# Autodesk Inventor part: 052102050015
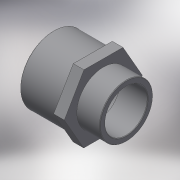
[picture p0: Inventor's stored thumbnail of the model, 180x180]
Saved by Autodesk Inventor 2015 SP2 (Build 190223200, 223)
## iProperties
Created: 2017-10
Part Number: 052102050015
Material: Generic
Description: PLASSON SOCKET NIPPLE THR-CE 63(50)-1.1/2"
Document SubType Name: Modeling
Designer: KIM
Density: 1 g/cm^3
Appearance: Default
Author: KIM
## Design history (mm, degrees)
derived "052102.ipt"
feature "Solid1::052102.ipt"
tag "TaggingFeature1"
body "Solid1"
other parameters: "d0" = 76, "d2" = 65, "d13" = 0, "d14" = 0.5, "d17" = 38, "d18" = 26.4, "d19" = 63, "d21" = 47.803, "d22" = 31, "d23" = 47.5, "d24" = 38.2424, "d25" = 22, "d26" = -38, "R_" = 47.803, "C_" = 65, "B_" = 12, "L_" = 38, "lt_" = 22, "H_" = 76, "D_" = 63, "l_" = 31
